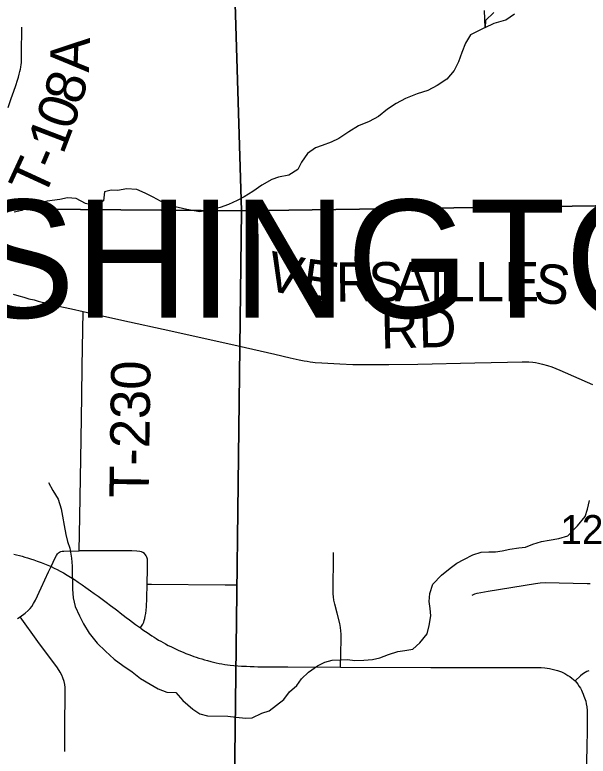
# Model space of a CAD drawing. Extents: x -87 to 2145, y -2128 to 440.
# Drawn here: x -43.13 to -42.301, y -694.892 to -693.821 of the extents above; entities that cross this region are included whole.
import ezdxf

# ---------------------------------------------------------------- set-up
doc = ezdxf.new("R2010")
doc.units = 0
for name, color, linetype in [('GM_X_City_Street', 7, 'Continuous'), ('GM_X_County_Road', 7, 'Continuous'), ('GM_X_County_Road_Text', 7, 'Continuous'), ('GM_X_Minor_Lake', 7, 'Continuous'), ('GM_X_Minor_River', 7, 'Continuous'), ('GM_X_Section', 7, 'Continuous'), ('GM_X_Section_Text', 7, 'Continuous'), ('GM_X_State_Route', 7, 'Continuous'), ('GM_X_Township_Road', 7, 'Continuous'), ('GM_X_Township_Road_Text', 7, 'Continuous'), ('GM_X_Township_Text', 7, 'Continuous')]:
    doc.layers.add(name, color=color, linetype=linetype)

msp = doc.modelspace()

# ---------------------------------------------------------------- linework, layer by layer
at = {"layer": 'GM_X_City_Street'}
for points in [[(-42.4691, -694.6597), (-42.4652, -694.6578), (-42.4616, -694.6566), (-42.4457, -694.6538), (-42.3772, -694.643), (-42.3705, -694.642), (-42.3636, -694.6415), (-42.3026, -694.6427), (-42.2985, -694.643)], [(-42.3003, -694.7692), (-42.3031, -694.7702), (-42.3057, -694.7715), (-42.3093, -694.7738), (-42.3125, -694.7765), (-42.3199, -694.7834)]]:
    msp.add_lwpolyline(points, dxfattribs=at)
at = {"layer": 'GM_X_County_Road'}
for points in [[(-43.1322, -694.2249), (-43.1241, -694.2271), (-43.117, -694.2291), (-43.1095, -694.2312), (-43.1021, -694.2331), (-43.0961, -694.2347), (-43.0904, -694.2361), (-43.0839, -694.2377), (-43.0773, -694.2393), (-43.0705, -694.2409), (-43.0597, -694.2433), (-43.0482, -694.246), (-43.0312, -694.2498)], [(-43.0312, -694.2498), (-42.9755, -694.2621), (-42.9044, -694.2775), (-42.8073, -694.2992), (-42.7541, -694.3116), (-42.7322, -694.3166), (-42.7189, -694.3194), (-42.7116, -694.3209), (-42.7072, -694.3217), (-42.7031, -694.3224), (-42.6992, -694.3229), (-42.6957, -694.3233), (-42.6864, -694.3241), (-42.6604, -694.3255), (-42.6412, -694.3261), (-42.6169, -694.3265), (-42.5896, -694.3265), (-42.5474, -694.3259), (-42.4653, -694.324), (-42.4181, -694.3229), (-42.3969, -694.3225), (-42.3869, -694.3227), (-42.3815, -694.3231), (-42.3773, -694.3236), (-42.3733, -694.3244), (-42.3671, -694.3258), (-42.3599, -694.3278), (-42.354, -694.3299), (-42.3424, -694.3346), (-42.2952, -694.3554)]]:
    msp.add_lwpolyline(points, dxfattribs=at)
at = {"layer": 'GM_X_Minor_Lake'}
msp.add_lwpolyline([(-42.4374, -693.8176), (-42.4495, -693.8291), (-42.4501, -693.8393), (-42.437, -693.8328), (-42.4205, -693.8283), (-42.4077, -693.8195)], dxfattribs=at)
at = {"layer": 'GM_X_Minor_River'}
for points in [[(-42.4501, -693.8393), (-42.451, -693.8146)], [(-42.4501, -693.8393), (-42.4716, -693.8501), (-42.4787, -693.8617), (-42.484, -693.8756), (-42.4889, -693.8887), (-42.4952, -693.9014), (-42.5058, -693.9141), (-42.5197, -693.9232), (-42.5328, -693.9304), (-42.5486, -693.935), (-42.5655, -693.9417), (-42.5786, -693.949), (-42.5913, -693.9574), (-42.6045, -693.968), (-42.6176, -693.9749), (-42.6334, -693.9813), (-42.6473, -693.99), (-42.6616, -693.9999), (-42.6728, -694.0049), (-42.6858, -694.0098), (-42.6954, -694.0134), (-42.707, -694.0214), (-42.7157, -694.0341), (-42.7209, -694.0445), (-42.734, -694.0529), (-42.749, -694.0556), (-42.7586, -694.0591), (-42.7728, -694.067), (-42.786, -694.0762), (-42.7987, -694.0838), (-42.8084, -694.0892), (-42.8211, -694.0953), (-42.8333, -694.0992), (-42.8471, -694.1026), (-42.8628, -694.1056), (-42.8814, -694.1024), (-42.8939, -694.0994), (-42.9034, -694.0973), (-42.9192, -694.0904), (-42.9302, -694.0845), (-42.9415, -694.0785), (-42.9535, -694.0736), (-42.9684, -694.0725), (-42.981, -694.0748), (-42.9905, -694.0745), (-43.0005, -694.0769), (-43.0019, -694.0897), (-43.0143, -694.097), (-43.0279, -694.0936), (-43.0411, -694.0864), (-43.054, -694.0853), (-43.0647, -694.088), (-43.0834, -694.0902), (-43.0976, -694.094), (-43.1084, -694.0986), (-43.1199, -694.1036), (-43.1307, -694.1063)], [(-43.0814, -694.4967), (-43.0748, -694.5083), (-43.0675, -694.521), (-43.0628, -694.5351), (-43.0612, -694.5454), (-43.0588, -694.5591), (-43.056, -694.5721), (-43.0536, -694.582), (-43.0504, -694.5916), (-43.048, -694.606), (-43.0472, -694.6178), (-43.047, -694.628), (-43.0465, -694.641), (-43.0464, -694.6508), (-43.0455, -694.6634), (-43.0427, -694.6759), (-43.0366, -694.6894), (-43.0307, -694.7009), (-43.0223, -694.7148), (-43.0108, -694.7291), (-42.9988, -694.7408), (-42.9865, -694.7522), (-42.9738, -694.7612), (-42.9606, -694.7707), (-42.9483, -694.7801), (-42.9344, -694.7885), (-42.9227, -694.7952), (-42.9102, -694.8001), (-42.8973, -694.8005), (-42.8869, -694.8117), (-42.8727, -694.8243), (-42.8626, -694.8314), (-42.8516, -694.8339), (-42.8223, -694.8347), (-42.8101, -694.8362), (-42.7964, -694.8373), (-42.7869, -694.8368), (-42.773, -694.8304), (-42.7623, -694.8268), (-42.7518, -694.8188), (-42.7413, -694.8103), (-42.7331, -694.7996), (-42.7222, -694.7904), (-42.7155, -694.7807), (-42.7054, -694.7711), (-42.6926, -694.7616), (-42.6819, -694.7565), (-42.6715, -694.7534), (-42.6585, -694.753), (-42.649, -694.7529), (-42.6384, -694.7539), (-42.6254, -694.7535), (-42.6128, -694.7527), (-42.6025, -694.7503), (-42.5898, -694.7453), (-42.5764, -694.7411), (-42.5664, -694.7395), (-42.5546, -694.7375), (-42.5445, -694.7287), (-42.5339, -694.7157), (-42.531, -694.7037), (-42.5288, -694.6897), (-42.5297, -694.679), (-42.5313, -694.6688), (-42.53, -694.6574), (-42.5258, -694.6439), (-42.5134, -694.6306), (-42.5009, -694.6207), (-42.4909, -694.6133), (-42.4812, -694.6083), (-42.4678, -694.6014), (-42.4559, -694.5976), (-42.4448, -694.5971), (-42.4353, -694.597), (-42.4254, -694.5957), (-42.4143, -694.5933), (-42.4016, -694.5914), (-42.3917, -694.5901), (-42.3813, -694.5859), (-42.3687, -694.582), (-42.3576, -694.58), (-42.3438, -694.5777), (-42.3308, -694.5739), (-42.3167, -694.5595), (-42.3058, -694.5461), (-42.3021, -694.5356), (-42.2996, -694.5228)]]:
    msp.add_lwpolyline(points, dxfattribs=at)
at = {"layer": 'GM_X_Section'}
for points in [[(-43.8397, -693.0904), (-43.8105, -693.0906), (-42.8334, -693.0959), (-42.8025, -694.1044), (-43.8497, -694.0955)], [(-42.8008, -693.0943), (-41.7996, -693.0924), (-41.8129, -694.0902), (-42.8025, -694.1044), (-42.8334, -693.0959)], [(-43.8497, -694.0955), (-42.8025, -694.1044), (-42.8144, -695.0901), (-43.8653, -695.0793)], [(-41.8129, -694.0902), (-41.8074, -695.0971), (-42.8144, -695.0901), (-42.8025, -694.1044)]]:
    msp.add_lwpolyline(points, close=True, dxfattribs=at)
at = {"layer": 'GM_X_State_Route'}
for p, q in [((-42.3026, -694.8446), (-42.3027, -694.8503)), ((-42.3027, -694.8503), (-42.3028, -694.8597))]:
    msp.add_line(p, q, dxfattribs=at)
for points in [[(-43.1314, -694.6005), (-43.1274, -694.6014), (-43.1232, -694.6024), (-43.1192, -694.6035), (-43.1155, -694.6046), (-43.1117, -694.6057), (-43.1072, -694.6072), (-43.1025, -694.6088), (-43.0977, -694.6104), (-43.0921, -694.6125), (-43.0869, -694.6145), (-43.0824, -694.6163), (-43.0776, -694.6184), (-43.0729, -694.6206), (-43.069, -694.6225), (-43.0646, -694.6248), (-43.0598, -694.6275), (-43.0544, -694.6306), (-43.0495, -694.6335), (-43.0439, -694.6371), (-43.0382, -694.6408), (-43.0326, -694.6446), (-43.0272, -694.6484), (-43.0205, -694.6532), (-43.0151, -694.6571), (-43.0094, -694.6613), (-43.0037, -694.6655), (-42.9981, -694.6697), (-42.9915, -694.6747), (-42.9851, -694.6796), (-42.9813, -694.6824), (-42.9777, -694.6851), (-42.9734, -694.6884), (-42.969, -694.6918), (-42.9642, -694.6954), (-42.9599, -694.6986), (-42.9554, -694.7019), (-42.9513, -694.7049), (-42.9483, -694.707), (-42.9474, -694.7077), (-42.9433, -694.7106), (-42.9389, -694.7137), (-42.9354, -694.7161), (-42.9318, -694.7184), (-42.9287, -694.7204), (-42.9257, -694.7223), (-42.9221, -694.7245), (-42.9188, -694.7264), (-42.9154, -694.7283), (-42.9122, -694.7301), (-42.9083, -694.7322), (-42.9044, -694.7341), (-42.9007, -694.7359), (-42.8976, -694.7374), (-42.8939, -694.7392), (-42.8903, -694.7408), (-42.8868, -694.7423), (-42.8829, -694.7438), (-42.8787, -694.7455), (-42.8745, -694.747), (-42.8714, -694.7481), (-42.8677, -694.7493), (-42.8639, -694.7506), (-42.8598, -694.7518), (-42.8558, -694.753), (-42.8515, -694.7542), (-42.8469, -694.7554), (-42.8427, -694.7565), (-42.839, -694.7574), (-42.8346, -694.7583), (-42.8306, -694.759), (-42.8265, -694.7597), (-42.8225, -694.7603), (-42.8189, -694.7608), (-42.8135, -694.7613), (-42.8078, -694.7618), (-42.8024, -694.7622), (-42.7953, -694.7625), (-42.79, -694.7627), (-42.7841, -694.7629), (-42.7785, -694.7631), (-42.7703, -694.7632), (-42.763, -694.7633), (-42.7543, -694.7635), (-42.7353, -694.7634), (-42.6593, -694.7639), (-42.5289, -694.7641), (-42.4805, -694.7641), (-42.422, -694.7641), (-42.4211, -694.7641)], [(-42.4211, -694.7641), (-42.3797, -694.7641), (-42.3747, -694.7641), (-42.369, -694.7644), (-42.3641, -694.7648), (-42.3573, -694.7657), (-42.3512, -694.7669), (-42.3458, -694.7685), (-42.34, -694.7707), (-42.3349, -694.7731), (-42.3306, -694.7757), (-42.3279, -694.7774), (-42.325, -694.7795), (-42.3223, -694.7816), (-42.3199, -694.7834), (-42.3181, -694.7857), (-42.3164, -694.7881), (-42.3141, -694.7918), (-42.3126, -694.7942), (-42.3111, -694.7971), (-42.31, -694.7995), (-42.3086, -694.8029), (-42.3074, -694.8056), (-42.3064, -694.8082), (-42.3049, -694.8129), (-42.3041, -694.8166), (-42.3034, -694.821), (-42.3029, -694.8265), (-42.3026, -694.8372), (-42.3026, -694.8436), (-42.3026, -694.8446)], [(-42.3028, -694.8597), (-42.303, -694.8749), (-42.3046, -694.9596), (-42.3047, -694.9669), (-42.3054, -695.0026), (-42.3054, -695.0039), (-42.3065, -695.0664), (-42.307, -695.092), (-42.3077, -695.1168), (-42.3077, -695.1301), (-42.3079, -695.1584), (-42.3081, -695.1913), (-42.3084, -695.2192), (-42.3085, -695.2711)]]:
    msp.add_lwpolyline(points, dxfattribs=at)
at = {"layer": 'GM_X_Township_Road'}
for p, q in [((-43.0371, -694.5957), (-43.0361, -694.5467)), ((-42.8258, -694.6446), (-42.8088, -694.6448)), ((-43.126, -694.6935), (-43.1222, -694.6909))]:
    msp.add_line(p, q, dxfattribs=at)
for points in [[(-43.1397, -693.955), (-43.1352, -693.942), (-43.1313, -693.9311), (-43.1285, -693.9229), (-43.1261, -693.9156), (-43.1247, -693.9111), (-43.1235, -693.9068), (-43.1226, -693.9031), (-43.1218, -693.8996), (-43.1213, -693.8965), (-43.1208, -693.8929), (-43.1205, -693.8902), (-43.1203, -693.8874), (-43.1202, -693.8834), (-43.1201, -693.8771), (-43.1197, -693.8386)], [(-43.0361, -694.5467), (-43.034, -694.4341), (-43.0332, -694.372), (-43.0327, -694.3291), (-43.0312, -694.2498)], [(-43.0776, -694.6184), (-43.0716, -694.6056), (-43.0699, -694.6022), (-43.0684, -694.6), (-43.0669, -694.5986), (-43.0653, -694.5974), (-43.0634, -694.5966), (-43.0614, -694.5962), (-43.059, -694.596), (-43.0371, -694.5957)], [(-42.9385, -694.6437), (-42.938, -694.621), (-42.938, -694.6121), (-42.9384, -694.6079), (-42.9392, -694.605), (-42.9401, -694.6029), (-42.941, -694.6014), (-42.9425, -694.5996), (-42.9449, -694.598), (-42.9469, -694.5971), (-42.9495, -694.5964), (-42.9537, -694.5959), (-42.9608, -694.5957), (-42.9807, -694.5958), (-43.0371, -694.5957)], [(-42.6593, -694.7639), (-42.6582, -694.7235), (-42.6582, -694.7161), (-42.6592, -694.7062), (-42.6602, -694.7008), (-42.664, -694.6858), (-42.6676, -694.6726), (-42.6688, -694.6671), (-42.6694, -694.6621), (-42.6697, -694.6577), (-42.6692, -694.5982)], [(-43.1222, -694.6909), (-43.1149, -694.6855), (-43.1106, -694.6819), (-43.1079, -694.6791), (-43.1055, -694.6762), (-43.1028, -694.6719), (-43.1002, -694.6669), (-43.092, -694.649), (-43.0812, -694.6259), (-43.0776, -694.6184)], [(-42.9483, -694.707), (-42.9467, -694.7045), (-42.9449, -694.7017), (-42.9437, -694.6988), (-42.9429, -694.6962), (-42.942, -694.6932), (-42.9414, -694.6901), (-42.9408, -694.6862), (-42.9402, -694.6815), (-42.9398, -694.6766), (-42.939, -694.6639), (-42.9385, -694.6437)], [(-42.9385, -694.6437), (-42.9323, -694.6437), (-42.8258, -694.6446)], [(-43.0576, -694.8858), (-43.0575, -694.8299), (-43.0573, -694.8207), (-43.0571, -694.7996), (-43.0573, -694.7933), (-43.0578, -694.7889), (-43.0588, -694.7846), (-43.0604, -694.7791), (-43.0622, -694.7751), (-43.0643, -694.7712), (-43.0685, -694.7649), (-43.0969, -694.7265), (-43.1222, -694.6909)]]:
    msp.add_lwpolyline(points, dxfattribs=at)

# ---------------------------------------------------------------- texts
at = {"layer": 'GM_X_County_Road_Text'}
for s, height, rotation, p in [('V', 0.0568, 347.6763, (-42.7705, -694.2174)), ('E', 0.0568, 351.8118, (-42.7172, -694.2289)), ('R', 0.0568, 0.5842, (-42.6657, -694.2356)), ('S', 0.0568, 0.0095, (-42.6192, -694.2351)), ('A', 0.0568, 0.0131, (-42.5808, -694.2351)), ('I', 0.0568, 0.0078, (-42.5308, -694.2351)), ('L', 0.0568, 0.0107, (-42.5075, -694.2351)), ('L', 0.0568, 0.0086, (-42.465, -694.2351)), ('E', 0.0568, 0.0107, (-42.4225, -694.2351)), ('S', 0.0568, 352.2119, (-42.382, -694.2349)), ('RD', 0.05682, 1.4672, (-42.6006, -694.3034))]:
    msp.add_text(s, height=height, rotation=rotation, dxfattribs=at).set_placement(p)
at = {"layer": 'GM_X_Section_Text'}
msp.add_text('12', height=0.04186, rotation=0, dxfattribs=at).set_placement((-42.3415, -694.5858))
at = {"layer": 'GM_X_Township_Road_Text'}
for s, height, rotation, p in [('A', 0.0568, 87.9958, (-43.0229, -693.9046)), ('8', 0.0568, 74.3702, (-43.0345, -693.9529)), ('0', 0.0568, 70.9621, (-43.0471, -693.9895)), ('1', 0.0568, 69.0227, (-43.0603, -694.0241)), ('-', 0.0568, 66.6913, (-43.0705, -694.0479)), ('T', 0.0568, 65.2656, (-43.0889, -694.0879)), ('T-230', 0.05682, 89.1629, (-42.9366, -694.5194))]:
    msp.add_text(s, height=height, rotation=rotation, dxfattribs=at).set_placement(p)
at = {"layer": 'GM_X_Township_Text'}
msp.add_text('WASHINGTON', height=0.17045, rotation=0, dxfattribs=at).set_placement((-43.5623, -694.2587))

doc.saveas('drawing.dxf')
